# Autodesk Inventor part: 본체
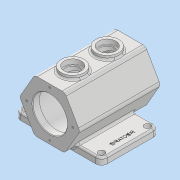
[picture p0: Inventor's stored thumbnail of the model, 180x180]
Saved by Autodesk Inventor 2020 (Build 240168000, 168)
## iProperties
Created: 2021-06
Part Number: 본체
Material: 일반
Document SubType Name: Modeling
Designer: MIRAE
Density: 1 g/cm^3
Appearance: 기본값
Author: MIRAE
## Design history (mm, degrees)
sketch "스케치3" dims "d2" = 105
  geometry: L1 (26.25, 45.466)-(52.5, 0); L2 (52.5, 0)-(26.25, -45.466); L3 (26.25, -45.466)-(-26.25, -45.466); L4 (-26.25, -45.466)-(-52.5, 0); L5 (-52.5, 0)-(-26.25, 45.466); L6 (-26.25, 45.466)-(26.25, 45.466); 3 further points
  constraints: 12 end point, 2 coincident, 1 horizontal alignment, 16 other
extrude "돌출1" new body sketch "스케치3" stored distance "d3" = 140; taper "d4" = 0 deg
node "작업 평면1"
sketch "스케치4"
  geometry: L1 (-75, 45)-(75, 45); L2 (75, 45)-(75, -55); L3 (75, -55)-(-75, -55); L4 (-75, -55)-(-75, 45); L5 (26.25, -70)-(-26.25, -70) reference; L6 (-26.25, 70)-(26.25, 70) reference; L7 (0, 0)-(0, 176.664)
  constraints: 10 end point, 2 parallel, 1 horizontal, 1 perpendicular, 1 vertical, 1 other
  dimensions: "d6" = 15 distance between parallel lines of L5 L3; "d7" = 25 distance between parallel lines of L6 L1; "d8" = 150 distance between parallel lines of L4 L2
extrude "돌출2" join sketch "스케치4" distance "d9" = 12; taper "d10" = 0 deg
sketch "스케치5"
  geometry: L1 (-70, 0)-(70, 0) reference; L2 (70, 0)-(70, 45.466) reference; L3 (-70, 0)-(70, 0); L4 (70, 0)-(70, 30); L5 (70, 30)-(-70, 30); L6 (-70, 30)-(-70, 0); L7 (-58, 0)-(58, 0); L8 (58, 0)-(58, 37.5); L9 (58, 37.5)-(-58, 37.5); L10 (-58, 37.5)-(-58, 0); 3 further points
  constraints: 16 end point, 4 parallel, 2 horizontal, 2 perpendicular, 2 point on line
  dimensions: "d11" = 60 diameter of L5 L1; "d12" = 75 diameter of L9 L1; "d13" = 12 distance between parallel lines of L6 L10; "d14" = 12 distance between parallel lines of L2 L8
revolve "회전1" sketch "스케치5" stored, may be unused: angle "d15" = 90 deg
node "작업 평면2"
sketch "스케치6"
  geometry: L1 (26.25, -70)-(-26.25, -70) reference; C1 r 20 at (0, -30); C2 r 20 at (0, 30); 1 further point
  constraints: 2 centre point, 2 vertical alignment
  dimensions: "d17" = 40 diameter of C1; "d18" = 40 diameter of C2; "d19" = 60 distance of C2.centre C1.centre; "d20" = 40 distance from line of L1 C1.centre
extrude "돌출3" join sketch "스케치6" stored distance "d21" = 12; taper "d22" = 0 deg
sketch "스케치7"
  geometry: C1 r 20 at (0, 0) reference; 2 further points
  constraints: 1 coincident
hole "구멍1" sketch "스케치7" at (0, 0) diameter "d23" = 25; stored, may be unused: countersink angle "d27" = 90 deg, drill point angle "d29" = 118 deg; dims "d24" = 6, "d25" = 30, "d26" = 8, "d28" = 8
sketch "스케치9"
  geometry: C1 r 30 at (0, 0) reference; 2 further points
  constraints: 1 vertical alignment
  dimensions: "d33" = 40 distance of C1.centre point (0, 40)
hole "구멍2" sketch "스케치9" at (0, 40) diameter "d34" = 3.242; stored, may be unused: countersink angle "d38" = 90 deg, drill point angle "d40" = 118 deg; dims "d35" = 8, "d36" = 30, "d37" = 8, "d39" = 10
sketch "스케치10"
  geometry: L1 (0, 0)-(28.284, -28.284); L2 (0, 0)-(0, -76.516)
  constraints: 4 end point, 1 vertical
  dimensions: "d44" = 45 deg angle of L2 L1; "d45" = 40 distance of L1.start L1.end
hole "구멍3" sketch "스케치10" at (28.284, -28.284) diameter "d46" = 3.242; stored, may be unused: countersink angle "d50" = 90 deg, drill point angle "d52" = 118 deg; dims "d47" = 8, "d48" = 30, "d49" = 8, "d51" = 10
fillet "모깎기1" dims "d56" = 10
sketch "스케치11"
  geometry: A1 r 10 centre (-65, 35) between (-65, 45) and (-75, 35) reference; A2 r 10 centre (-65, -45) between (-75, -45) and (-65, -55) reference; A3 r 10 centre (65, -45) between (65, -55) and (75, -45) reference; A4 r 10 centre (65, 35) between (75, 35) and (65, 45) reference; 5 further points
  constraints: 4 coincident
hole "구멍4" sketch "스케치11" at (-65, 35), (-65, -45), (65, -45), (65, 35) diameter "d57" = 11; stored, may be unused: countersink angle "d61" = 90 deg, drill point angle "d63" = 118 deg; dims "d58" = 8, "d59" = 30, "d60" = 8, "d62" = 10
sketch "스케치12"
  geometry: L1 (75, -45)-(75, 35) reference; L2 (65, 45)-(30.561, 45) reference; 2 further points
  constraints: 1 other
  dimensions: "d64" = 14 distance from line of L1 point (61, -5); "d65" = 50 distance from line of L2 point (61, -5)
feature "엠보싱1" sketch "스케치12" dims "d2" = 105, "d66" = 0.5, "d67" = 0
fillet "모깎기5" dims "d71" = 3
fillet "모깎기6" dims "d72" = 8
fillet "모깎기7" dims "d73" = 3
fillet "모깎기8" dims "d74" = 5
fillet "모깎기9" dims "d75" = 3
chamfer "모따기1" distance "d76" = 1; stored, may be unused: second distance "d77" = 2, angle "d78" = 45 deg
sketch "스케치14"
  geometry: L1 (0, 62.153)-(-91.717, 62.153); L2 (-91.717, 62.153)-(-91.717, -80.579); L3 (-91.717, -80.579)-(0, -80.579); L4 (0, -80.579)-(0, 62.153); 1 further point
  constraints: 8 end point, 2 parallel, 1 horizontal, 1 perpendicular
extrude "돌출4" cut sketch "스케치14" extent not by distance; stored distance "d79" = 0; taper "d80" = 0 deg
node "솔리드1"
pattern_linear "직사각형 패턴1" dims "d32" = 60
pattern_circular "원형 패턴1" dims angle "d42" = 360 deg
pattern_circular "원형 패턴2" dims angle "d54" = 360 deg
feature "A9D066F2-1C7D-4E18-AEED-F7BC21143FA4" dims "d57" = 11, "d58" = 8, "d59" = 30, "d60" = 8, "d61" = 90 deg, "d62" = 10, "d63" = 118 deg
other parameters: "d16" = 52.5
